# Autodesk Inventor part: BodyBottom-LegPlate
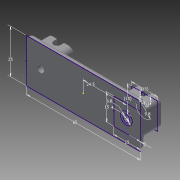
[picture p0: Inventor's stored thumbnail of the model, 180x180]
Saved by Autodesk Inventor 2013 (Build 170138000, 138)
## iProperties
Created: 2013-03
Part Number: BodyBottom-LegPlate
Material: Generic
Document SubType Name: Modeling
Designer: frankenteddy
Density: 1 g/cm^3
Author: frankenteddy
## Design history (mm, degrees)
sketch "Sketch1"
  geometry: L1 (-32.5, 12.5)-(32.5, 12.5); L2 (32.5, 12.5)-(32.5, -12.5); L3 (32.5, -12.5)-(-32.5, -12.5); L4 (-32.5, -12.5)-(-32.5, 12.5); L5 (-24.5, 12.5)-(-24.5, -12.5); L6 (-32.5, 7.5)-(-17.5, 7.5); L7 (-17.5, 7.5)-(-17.5, -7.5); L8 (-17.5, -7.5)-(-32.5, -7.5); L9 (-32.5, -7.5)-(-32.5, 7.5); C1 r 2 at (-24.5, 0); C2 r 3.4 at (-24.5, 0); 4 further points
  constraints: 18 end point, 4 midpoint, 4 parallel, 3 perpendicular, 2 centre point, 2 horizontal, 2 horizontal alignment, 2 point on line, 1 coincident, 1 vertical alignment
  dimensions: "d0" = 65 distance of L2.end L3.end; "d2" = 25 distance of L1.end L2.end; "d5" = 4 diameter of C1; "d6" = 15 distance of L7.end L8.end; "d7" = 15 distance of L6.end L7.end; "d51" = 0 distance between parallel lines of L4 L9; "d56" = 6.8 diameter of C2; "d61" = 24.5 distance from line of point (0, 0) L5
extrude "Extrusion1" new body sketch "Sketch1" distance "d9" = 3; taper "d10" = 0 deg
extrude "Extrusion2" cut sketch "Sketch1" distance "d11" = 3; taper "d12" = 0 deg
mirror "Mirror1"
extrude "Extrusion3" join sketch "Sketch1" distance "d13" = 10; taper "d14" = 0 deg
sketch "Sketch2"
  geometry: L1 (17.5, 0)-(32.5, 0); L2 (20.1, 0)-(29.9, 0); L3 (32.5, 7.5)-(17.5, 7.5); L4 (17.5, 7.5)-(17.5, -7.5); L5 (17.5, -7.5)-(32.5, -7.5); L6 (32.5, -7.5)-(32.5, 7.5); L7 (32.5, 7.5)-(17.5, 7.5) reference; L8 (23, -3.5)-(25, -3.5); L9 (23, -7.5)-(23, -3.5); L10 (25, -7.5)-(25, 7.5); L11 (25, -3.5)-(25, -7.5); L12 (25, -7.5)-(23, -7.5); L13 (25, -7.5)-(27, -7.5); L14 (27, -7.5)-(27, -3.5); L15 (27, -3.5)-(25, -3.5); L16 (25, -3.5)-(25, -7.5); A1 r 4.9 centre (25, 0) between (20.1, 0) and (21.977, -3.856); A2 r 4.9 centre (25, 0) between (25, -4.9) and (29.9, 0); A3 r 4.9 centre (25, 0) between (21.977, -3.856) and (25, -4.9); 5 further points
  constraints: 30 end point, 7 midpoint, 7 point on circle, 6 parallel, 4 point on line, 3 centre point, 3 collinear, 3 horizontal, 2 perpendicular, 1 vertical alignment
  dimensions: "d15" = 9.8 diameter of A1; "d36" = 15 distance of L5.end L4.end (derived); "d37" = 15 distance of L4.end L3.end (derived); "d42" = 4 distance of L9.start L8.start; "d43" = 2 distance of L8.start L8.end; "d47" = 2 distance of L15.end L14.end; "d48" = 4 distance of L14.end L13.end
extrude "Extrusion8" join sketch "Sketch2" distance "d40" = 2; taper "d41" = 0 deg
mirror "Mirror6"
revolve "Revolution1" stored, may be unused: angle "d16" = 90 deg
mirror "Mirror2"
revolve "Revolution4" stored, may be unused: angle "d44" = 90 deg
extrude "Extrusion9" cut sketch "Sketch2" distance "d45" = 2.5; taper "d46" = 0 deg
extrude "Extrusion10" cut sketch "Sketch2" distance "d49" = 2.5; taper "d50" = 0 deg
mirror "Mirror7"
fillet "Fillet6" dims "d53" = 3
mirror "Mirror9"
extrude "Extrusion12" cut sketch "Sketch1" distance "d57" = 20; taper "d58" = 0 deg
extrude "Extrusion13" join sketch "Sketch1" distance "d59" = 2; taper "d60" = 0 deg
fillet "Fillet7" dims "d62" = 2
fillet "Fillet8" dims "d63" = 2
mirror "Mirror10"
body "Solid1"
